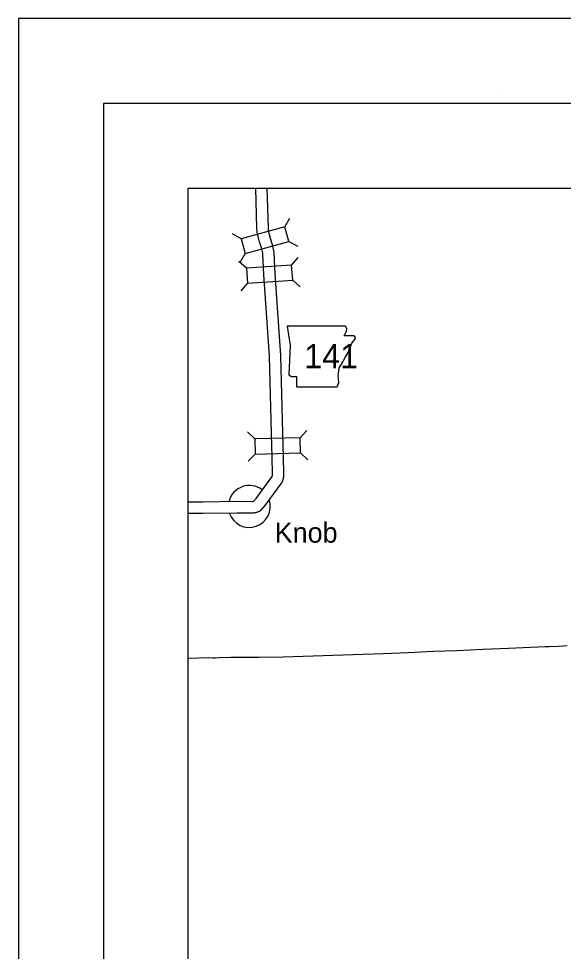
# Model space of a CAD drawing. Extents: x -0.3 to 2.65, y 0 to 1.9.
# Drawn here: x 0 to 0.1338, y 0.6874 to 0.9167 of the extents above; entities that cross this region are included whole.
import ezdxf

# ---------------------------------------------------------------- set-up
doc = ezdxf.new("R2010")
doc.units = 0
for name, color, linetype in [('DSN_DRFT_DNC', 7, 'Continuous'), ('Level 21', 7, 'Continuous'), ('Level 22', 7, 'Continuous'), ('Level 23', 7, 'Continuous'), ('Level 24', 7, 'Continuous'), ('Level 38', 7, 'Continuous'), ('SHET_Border-Lines', 7, 'Continuous')]:
    doc.layers.add(name, color=color, linetype=linetype)

msp = doc.modelspace()

# ---------------------------------------------------------------- linework, layer by layer
at = {"layer": 'DSN_DRFT_DNC'}
msp.add_lwpolyline([(0.04166666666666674, 0.8750000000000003), (0.34166666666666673, 0.8750000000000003), (0.34166666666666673, 0.541666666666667), (0.04166666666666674, 0.541666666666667)], close=True, dxfattribs=at)
at = {"layer": 'Level 21'}
for points in [[(0.05768243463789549, 0.7979641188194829), (0.05834767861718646, 0.7987291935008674), (0.062246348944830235, 0.8040836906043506), (0.0623085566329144, 0.8041991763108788), (0.06234010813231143, 0.804366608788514), (0.06235557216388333, 0.8046037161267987), (0.062296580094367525, 0.8090394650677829), (0.06220942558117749, 0.8115962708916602), (0.06162393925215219, 0.8337132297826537), (0.060237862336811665, 0.8537817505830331), (0.060011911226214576, 0.8587802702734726), (0.05997439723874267, 0.8590296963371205), (0.05962354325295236, 0.8603213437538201), (0.05918883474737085, 0.861836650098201), (0.05884321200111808, 0.8630814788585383), (0.058708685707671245, 0.8635906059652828), (0.05858977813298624, 0.8642423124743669), (0.058549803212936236, 0.8651011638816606), (0.058272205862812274, 0.8749999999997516)], [(0.05942107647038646, 0.7956773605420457), (0.0605497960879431, 0.7969754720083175), (0.06463209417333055, 0.8025821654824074), (0.06486875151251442, 0.8030214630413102), (0.0650244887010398, 0.8034240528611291), (0.06513554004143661, 0.8040133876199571), (0.06516928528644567, 0.8045307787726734), (0.06510843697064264, 0.8091060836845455), (0.06502065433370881, 0.8116813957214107), (0.06443386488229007, 0.8338473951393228), (0.06304597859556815, 0.8539421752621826), (0.06281491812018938, 0.8590536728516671), (0.06273132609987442, 0.8596094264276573), (0.0623324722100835, 0.8610777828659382), (0.06189559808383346, 0.8626006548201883), (0.0615578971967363, 0.863816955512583), (0.06145584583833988, 0.8642031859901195), (0.061390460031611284, 0.8645615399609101), (0.06136046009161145, 0.865205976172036), (0.06108580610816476, 0.8749999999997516)], [(0.057676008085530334, 0.797956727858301), (0.057682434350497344, 0.7979641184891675)], [(0.05768086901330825, 0.7979524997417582), (0.057516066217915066, 0.797917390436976), (0.05360745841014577, 0.7979318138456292), (0.045218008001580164, 0.7978299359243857), (0.04166666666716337, 0.797801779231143)], [(0.059422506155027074, 0.7956740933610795), (0.0585149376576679, 0.7952768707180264), (0.058353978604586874, 0.7952177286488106), (0.058190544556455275, 0.7951854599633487), (0.05810599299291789, 0.7951674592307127)], [(0.05810599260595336, 0.7951674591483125), (0.05797893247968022, 0.7951404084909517), (0.05772778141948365, 0.7951040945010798), (0.05361934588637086, 0.7951192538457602), (0.04524623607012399, 0.7950175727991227), (0.04166666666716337, 0.7949891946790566)]]:
    msp.add_lwpolyline(points, dxfattribs=at)
at = {"layer": 'Level 22'}
msp.add_lwpolyline([(0.06600666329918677, 0.8410841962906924), (0.06672038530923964, 0.8363260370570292), (0.06640317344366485, 0.8291094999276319), (0.06703759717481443, 0.8287129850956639), (0.06822714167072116, 0.8287129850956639), (0.06822714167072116, 0.8261753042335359), (0.07821927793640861, 0.8261753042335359), (0.07869508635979, 0.8272062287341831), (0.07853648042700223, 0.8288715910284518), (0.07877438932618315, 0.8307748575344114), (0.07964672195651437, 0.8322815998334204), (0.08020183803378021, 0.8333918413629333), (0.08099486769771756, 0.8345813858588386), (0.08147068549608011, 0.8358502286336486), (0.08186720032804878, 0.8368811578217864), (0.08258092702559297, 0.8377534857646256), (0.08273953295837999, 0.8383086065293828), (0.0824223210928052, 0.8387051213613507), (0.07996393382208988, 0.8387051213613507), (0.080519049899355, 0.8398153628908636), (0.08059835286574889, 0.8405290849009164), (0.08026947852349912, 0.84107720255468)], close=True, dxfattribs=at)
at = {"layer": 'Level 23'}
msp.add_lwpolyline([(0.04166666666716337, 0.7594087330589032), (0.046674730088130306, 0.7596171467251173), (0.047735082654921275, 0.7595590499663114), (0.04837284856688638, 0.7595336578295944), (0.049260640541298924, 0.7595920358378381), (0.05207691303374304, 0.7596782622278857), (0.055896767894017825, 0.7597232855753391), (0.05895979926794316, 0.7597143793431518), (0.06501877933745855, 0.7597413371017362), (0.0895290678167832, 0.7605924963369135), (0.09570325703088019, 0.7608115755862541), (0.10193972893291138, 0.7611268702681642), (0.10772099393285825, 0.7613326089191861), (0.11416456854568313, 0.7616172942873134), (0.12034682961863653, 0.761874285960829), (0.12933376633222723, 0.7622829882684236), (0.13035445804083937, 0.7622894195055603), (0.13264490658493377, 0.7624142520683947), (0.1347763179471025, 0.7625336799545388)], dxfattribs=at)
at = {"layer": 'Level 24'}
for start, end in [(52.916111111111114, 165.67338333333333), (199.9062111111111, 17.605194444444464)]:
    msp.add_arc((0.05667760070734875, 0.7967413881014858), 0.0051562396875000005, start, end, dxfattribs=at)
at = {"layer": 'Level 38'}
for p, q in [((0.06541138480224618, 0.8654970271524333), (0.06662948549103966, 0.8676515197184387)), ((0.05467985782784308, 0.8625174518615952), (0.05252536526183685, 0.8637355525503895)), ((0.06640457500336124, 0.8619198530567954), (0.06855906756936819, 0.8607017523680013)), ((0.055673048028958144, 0.8589402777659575), (0.05445494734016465, 0.856785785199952)), ((0.06706952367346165, 0.8560975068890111), (0.06869485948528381, 0.8579640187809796)), ((0.055958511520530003, 0.855330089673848), (0.054091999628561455, 0.8569554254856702)), ((0.05621431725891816, 0.8516264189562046), (0.05458898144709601, 0.8497599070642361)), ((0.06732532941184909, 0.8523938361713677), (0.06919184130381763, 0.8507685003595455)), ((0.0579991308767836, 0.8133470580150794), (0.056203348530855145, 0.815050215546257)), ((0.06913270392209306, 0.8136417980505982), (0.07083585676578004, 0.8154375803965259)), ((0.05809737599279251, 0.8096358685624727), (0.05639422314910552, 0.8078400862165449)), ((0.06923094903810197, 0.8099306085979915), (0.07102673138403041, 0.8082274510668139))]:
    msp.add_line(p, q, dxfattribs=at)
for points in [[(0.06541138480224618, 0.8654970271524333), (0.05467985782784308, 0.8625174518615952), (0.055673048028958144, 0.8589402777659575), (0.06640457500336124, 0.8619198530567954)], [(0.05621431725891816, 0.8516264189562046), (0.06732532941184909, 0.8523938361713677), (0.06706952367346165, 0.8560975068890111), (0.055958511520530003, 0.855330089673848)], [(0.06913270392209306, 0.8136417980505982), (0.0579991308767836, 0.8133470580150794), (0.05809737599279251, 0.8096358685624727), (0.06923094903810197, 0.8099306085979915)]]:
    msp.add_lwpolyline(points, close=True, dxfattribs=at)
at = {"layer": 'SHET_Border-Lines'}
msp.add_line((0.11759163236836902, 0.8988149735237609), (0.11759163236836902, 0.8988149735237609), dxfattribs=at)
msp.add_line((0.11759163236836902, 0.8988149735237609), (0.11759163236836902, 0.8988149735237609), dxfattribs=at)
for points in [[(0, 0), (1.416666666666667, 0), (1.416666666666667, 0.9166666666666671), (0, 0.9166666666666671)], [(0.02083333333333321, 0.02083333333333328), (1.3958333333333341, 0.02083333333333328), (1.3958333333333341, 0.8958333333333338), (0.02083333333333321, 0.8958333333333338)]]:
    msp.add_lwpolyline(points, close=True, dxfattribs=at)

# ---------------------------------------------------------------- texts
at = {"layer": 'Level 22'}
msp.add_text('141', height=0.005939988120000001, dxfattribs=at).set_placement((0.0701368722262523, 0.8307107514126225))
at = {"layer": 'Level 24'}
msp.add_text('Knob', height=0.004949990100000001, dxfattribs=at).set_placement((0.06289687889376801, 0.7878401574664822))

doc.saveas('drawing.dxf')
